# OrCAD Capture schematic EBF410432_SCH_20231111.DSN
size A4; title: 鲁班猫摄像头24PIN-FPC线(异面); rev: V1.0; note: 鲁班猫摄像头24PIN-FPC线(异面); note: https://yehuosm.tmall.com
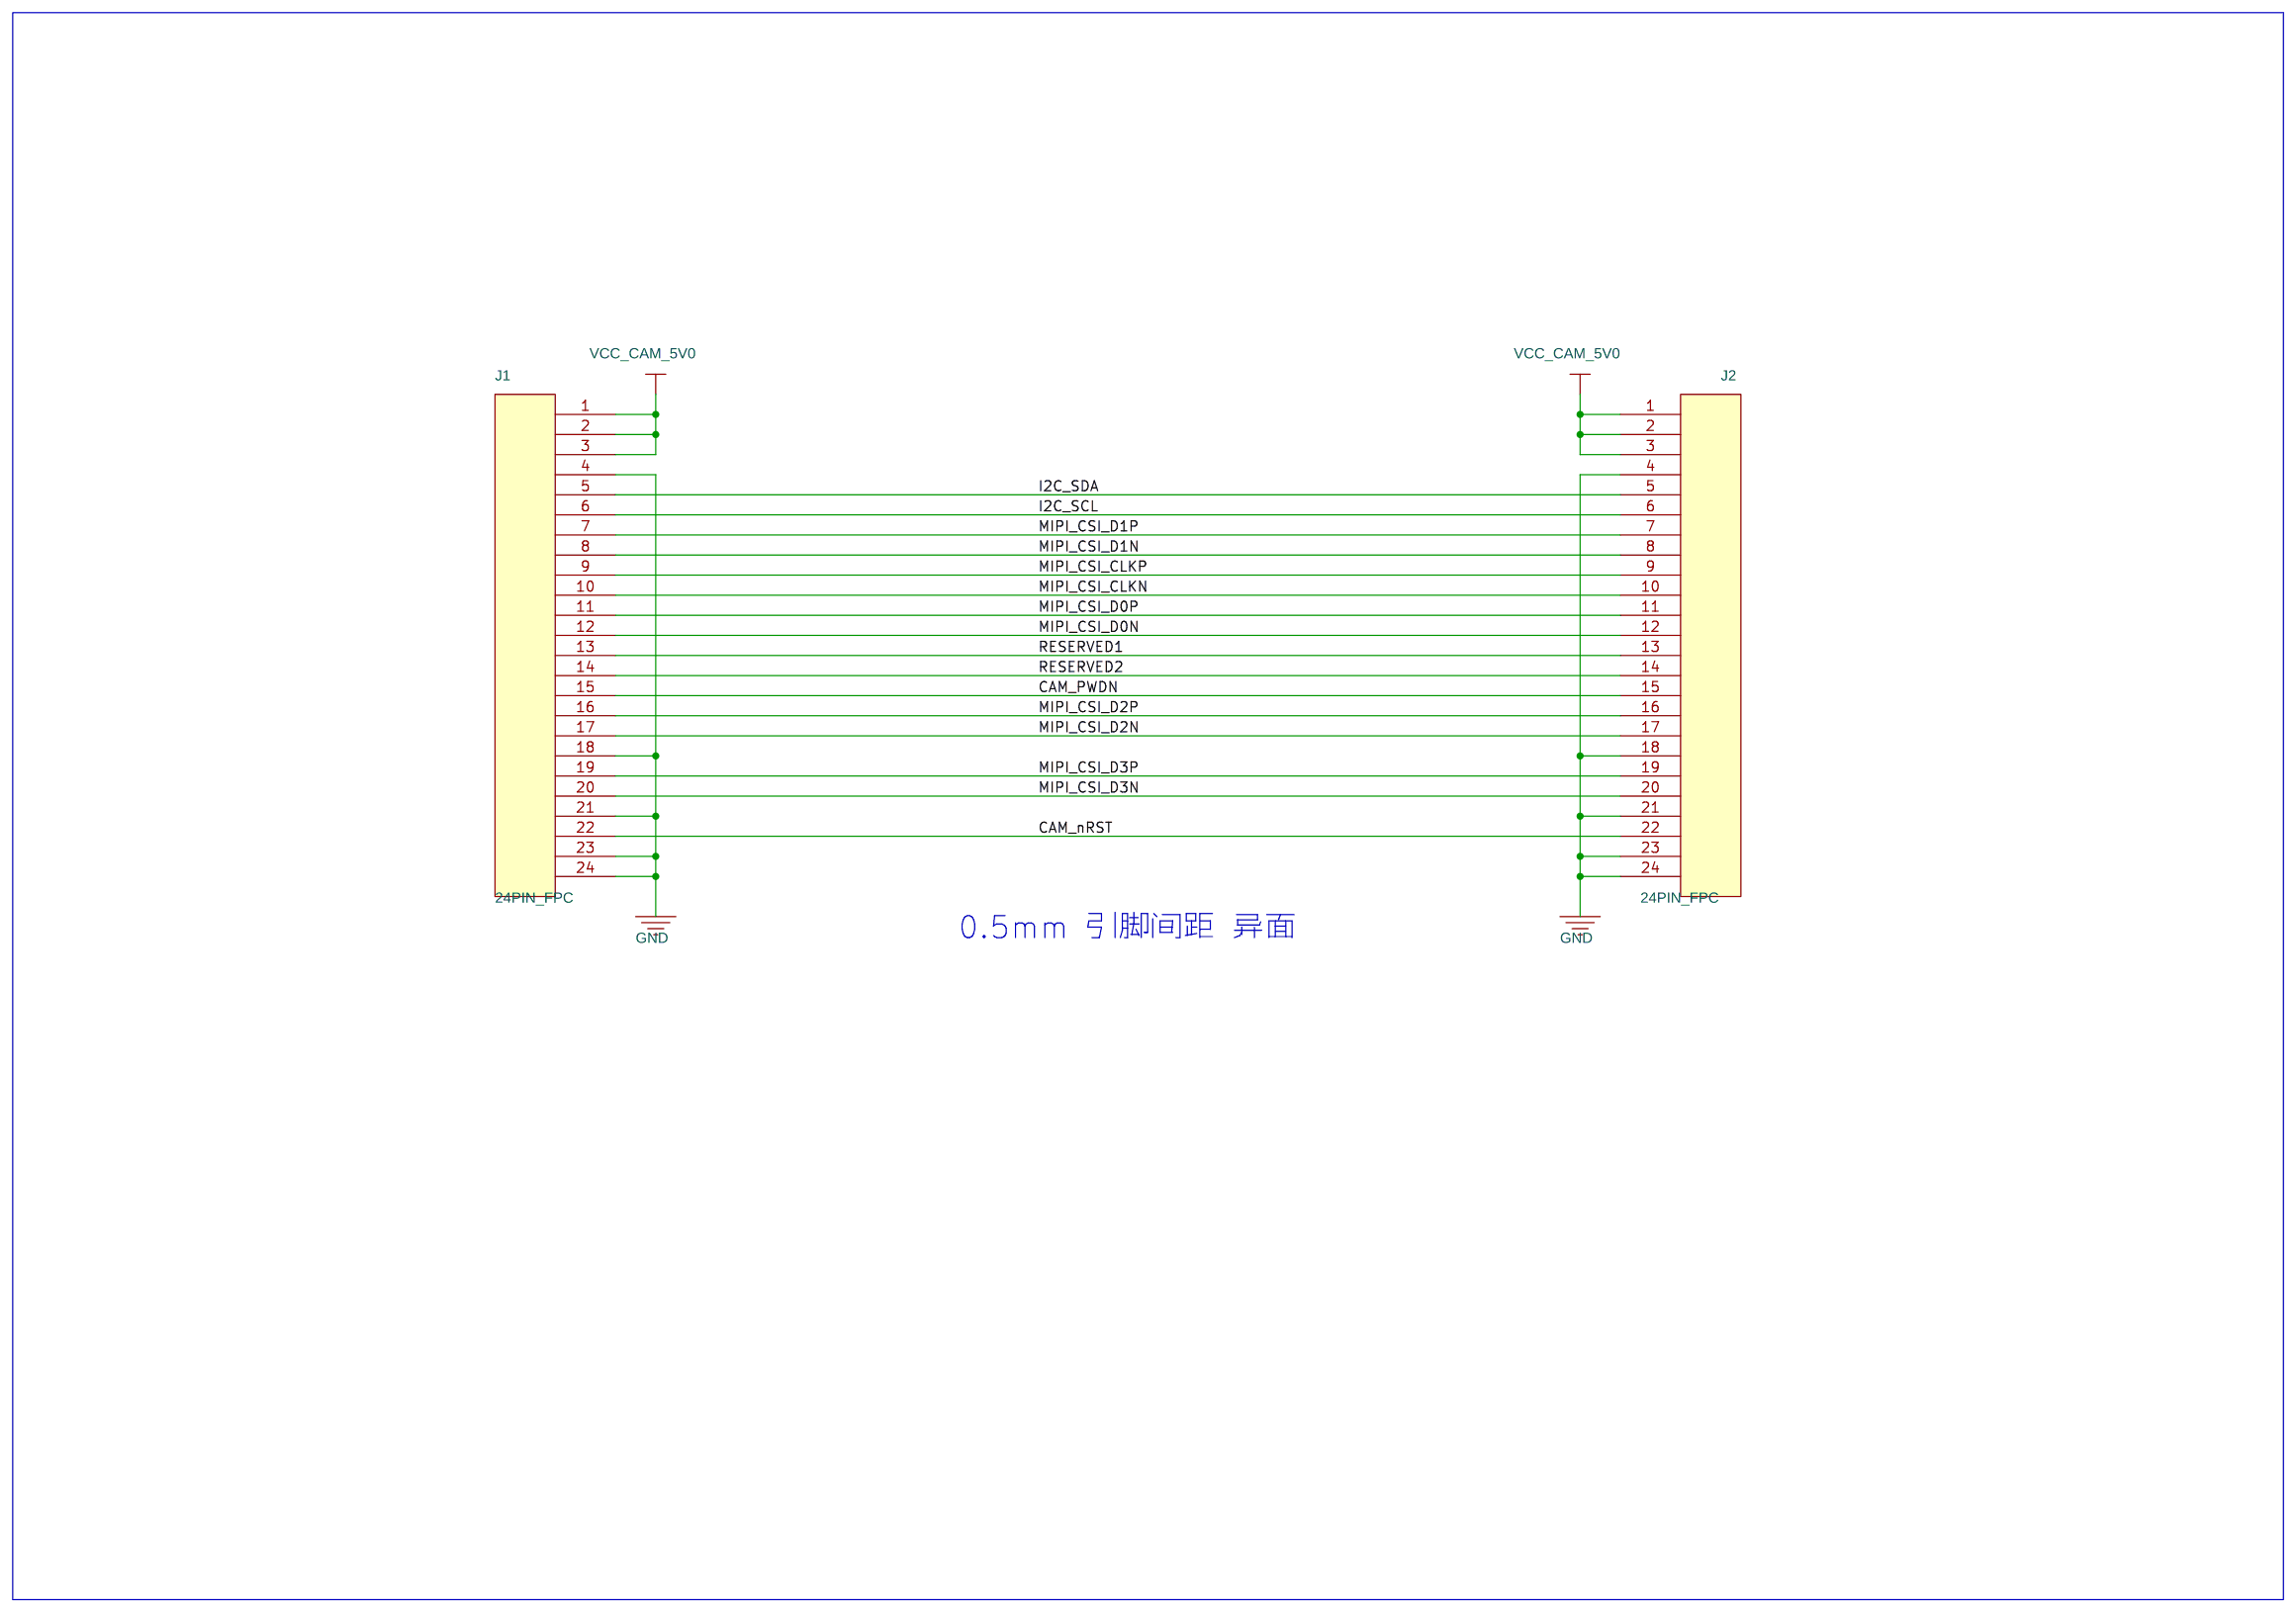
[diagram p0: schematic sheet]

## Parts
J1  24PIN_FPC
J2  24PIN_FPC

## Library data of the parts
J1 J2 = 24PIN_FPC

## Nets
GND: J1.4 J1.18 J1.21 J1.23 J1.24 J2.4 J2.18 J2.21 J2.23 J2.24
VCC_CAM_5V0: J1.1 J1.2 J1.3 J2.1 J2.2 J2.3
CAM_nRST: J1.22 J2.22
CAM_PWDN: J1.15 J2.15
I2C_SCL: J1.6 J2.6
I2C_SDA: J1.5 J2.5
MIPI_CSI_CLKN: J1.10 J2.10
MIPI_CSI_CLKP: J1.9 J2.9
MIPI_CSI_D0N: J1.12 J2.12
MIPI_CSI_D0P: J1.11 J2.11
MIPI_CSI_D1N: J1.8 J2.8
MIPI_CSI_D1P: J1.7 J2.7
MIPI_CSI_D2N: J1.17 J2.17
MIPI_CSI_D2P: J1.16 J2.16
MIPI_CSI_D3N: J1.20 J2.20
MIPI_CSI_D3P: J1.19 J2.19
RESERVED1: J1.13 J2.13
RESERVED2: J1.14 J2.14

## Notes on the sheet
- 0.5mm 引脚间距 异面
